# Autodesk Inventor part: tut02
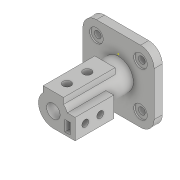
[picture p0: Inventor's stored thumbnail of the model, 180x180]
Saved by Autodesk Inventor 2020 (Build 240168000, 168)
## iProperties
Created: 2015-03
Part Number: tut02
Material: Generic
Document SubType Name: Modeling
Designer: Sandeep
Density: 1 g/cm^3
Appearance: Default
Author: Sandeep
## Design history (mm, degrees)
sketch "Sketch1"
  geometry: L1 (-32.5, -52.5)-(32.5, -52.5); L2 (52.5, -32.5)-(52.5, 32.5); L3 (32.5, 52.5)-(-32.5, 52.5); L4 (-52.5, 32.5)-(-52.5, -32.5); L5 (-52.5, -52.5)-(52.5, 52.5); L6 (52.5, -52.5)-(-52.5, 52.5); A1 r 20 centre (32.5, 32.5) between (52.5, 32.5) and (32.5, 52.5); A2 r 20 centre (32.5, -32.5) between (32.5, -52.5) and (52.5, -32.5); A3 r 20 centre (-32.5, -32.5) between (-52.5, -32.5) and (-32.5, -52.5); A4 r 20 centre (-32.5, 32.5) between (-32.5, 52.5) and (-52.5, 32.5); 1 further point
  constraints: 12 end point, 8 point on circle, 8 point on line, 8 tangent, 4 centre point, 2 equal radius, 2 midpoint, 2 parallel, 1 horizontal, 1 perpendicular
  dimensions: "d0" = 105 distance of L6.start L5.end; "d1" = 105 distance of L5.start L6.start; "d2" = 20 radius of A1; "d3" = 20 radius of A2
extrude "Extrusion1" new body sketch "Sketch1" distance "d4" = 12; taper "d5" = 0 deg
hole "Hole1" diameter "d8" = 10; stored, may be unused: countersink angle "d12" = 90 deg, drill point angle "d14" = 118 deg; dims "d9" = 6, "d10" = 20, "d11" = 2, "d13" = 8, "d15" = 10, "d16" = 10
hole "Hole2" diameter "d19" = 10; stored, may be unused: countersink angle "d23" = 90 deg, drill point angle "d25" = 118 deg; dims "d17" = 10, "d18" = 10, "d20" = 6, "d21" = 20, "d22" = 2, "d24" = 8
hole "Hole3" diameter "d28" = 10; stored, may be unused: countersink angle "d32" = 90 deg, drill point angle "d34" = 118 deg; dims "d26" = 10, "d27" = 10, "d29" = 6, "d30" = 20, "d31" = 2, "d33" = 8
hole "Hole4" diameter "d37" = 10; stored, may be unused: countersink angle "d41" = 90 deg, drill point angle "d43" = 118 deg; dims "d35" = 10, "d36" = 10, "d38" = 6, "d39" = 20, "d40" = 2, "d42" = 8
sketch "Sketch2"
  geometry: C1 r 22 at (0, 0); 1 further point
  constraints: 1 centre point, 1 coincident
  dimensions: "d44" = 44 diameter of C1
extrude "Extrusion2" join sketch "Sketch2" distance "d45" = 96; taper "d46" = 0 deg
sketch "Sketch3"
  geometry: L1 (-15, 16.093)-(-15, 25); L2 (15, 16.093)-(15, 25); L3 (-15, 25)-(15, 25); L4 (0, 0)-(20.619, 0); L5 (0, 6.043)-(0, 0); A1 r 22 centre (0, 0) between (15, 16.093) and (-15, 16.093); 1 further point
  constraints: 10 end point, 3 vertical, 2 horizontal, 2 point on circle, 1 centre point, 4 other
  dimensions: "d48" = 25 distance from line of point (0, 0) L3; "d49" = 30 distance of L1.end L2.end
extrude "Extrusion3" join sketch "Sketch3" distance "d51" = 76; taper "d52" = 0 deg
sketch "Sketch4"
  geometry: L1 (20.494, 8)-(32, 8); L2 (32, 8)-(32, -22); L3 (0, 0)-(37.067, 0); L4 (0, -22)-(32, -22); A1 r 22 centre (0, 0) between (20.494, 8) and (0, -22) reference; A2 r 22 centre (0, 0) between (0, -22) and (20.494, 8); 1 further point
  constraints: 8 end point, 5 point on circle, 2 horizontal, 2 perpendicular, 1 centre point, 1 concentric, 1 tangent
  dimensions: "d53" = 30 distance of L2.end L1.end; "d54" = 32 distance from line of L2 point (0, 0)
extrude "Extrusion4" join sketch "Sketch4" distance "d55" = 57; taper "d56" = 0 deg
sketch "Sketch5"
  geometry: L1 (17, -2)-(25, -2); L2 (25, -2)-(25, -18); L3 (25, -18)-(17, -18); L4 (17, -18)-(17, -2); 1 further point
  constraints: 8 end point, 2 parallel, 1 horizontal, 1 perpendicular
  dimensions: "d57" = 16 distance of L1.end L2.end; "d58" = 2 distance from line of point (0, 0) L1; "d59" = 25 distance from line of point (0, 0) L2; "d60" = 8 distance of L2.end L3.end
extrude "Extrusion5" cut sketch "Sketch5" distance "d61" = 50; taper "d62" = 0 deg
sketch "Sketch6"
  geometry: 1 further point
sketch "Sketch8"
  geometry: 1 further point
hole "Hole10" diameter "d113" = 10; stored, may be unused: countersink angle "d117" = 90 deg, drill point angle "d119" = 118 deg; dims "d111" = 15, "d112" = 15, "d114" = 6, "d115" = 4, "d116" = 2, "d118" = 96
hole "Hole11" diameter "d122" = 10; stored, may be unused: countersink angle "d126" = 90 deg, drill point angle "d128" = 118 deg; dims "d120" = 37, "d121" = 15, "d123" = 6, "d124" = 4, "d125" = 2, "d127" = 96
sketch "Sketch9"
  geometry: C1 r 10 at (0, 0); 1 further point
  constraints: 1 centre point, 1 coincident
  dimensions: "d129" = 20 diameter of C1
extrude "Extrusion7" cut sketch "Sketch9" distance "d130" = 96; taper "d131" = 0 deg
sketch "Sketch10"
  geometry: L1 (15, -0.369)-(15, 146.33); L2 (30, 0)-(30, 76) reference; L3 (0, 0)-(30, 0) reference; C1 r 6 at (15, 20); C2 r 6 at (15, 50); 1 further point
  constraints: 2 centre point, 2 end point, 2 point on line, 1 equal radius, 1 vertical
  dimensions: "d132" = 15 distance between parallel lines of L1 L2; "d133" = 12 diameter of C1; "d134" = 20 distance from line of C1.centre L3; "d135" = 30 distance of C2.centre C1.centre
extrude "Extrusion8" cut sketch "Sketch10" stored distance "d136" = 96; taper "d137" = 0 deg
body "Solid1"
